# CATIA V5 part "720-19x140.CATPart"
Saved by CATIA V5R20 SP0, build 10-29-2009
Part number: 720-19x140
Definition: NONE
Nomenclature: 720-19x140
Source: Unknown
Description: 720-19x140
Bounding box of the stored display mesh (mm): x 0 to 140, y -9.5 to 9.5, z -9.5 to 9.5
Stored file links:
  C:\Users\Utente\Desktop\IO LAVORO\3D X SITO CF\X SITO\720\720-19x140.CATPart
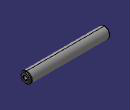
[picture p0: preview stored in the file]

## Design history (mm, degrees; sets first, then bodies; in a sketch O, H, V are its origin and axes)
Body1 "720-19x140" (main body)
  Solid1: solid without history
